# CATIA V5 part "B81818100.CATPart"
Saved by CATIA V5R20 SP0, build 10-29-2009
Part number: B81818100
Revision: 3
Definition: design
Nomenclature: B81818100
Source: made
Description: NOT SPECIFIED
Bounding box of the stored display mesh (mm): x -10.833 to 10.833, y -11 to 11, z 0 to 100
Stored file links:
  C:\Users\Raffaele\Desktop\3D X SITO CF\BOLEX\6-PILLAR REF 818\B81818100.CATPart
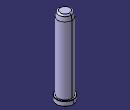
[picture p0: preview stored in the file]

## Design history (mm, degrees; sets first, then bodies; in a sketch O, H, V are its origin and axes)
Body1 "MANIFOLD_SOLID_BREP #370" (main body)
  Solid1: solid without history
